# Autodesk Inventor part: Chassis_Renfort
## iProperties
Created: 2009-02
Part Number: Chassis_Renfort
Document SubType Name: Sheet Metal
Designer: claivier
Author: claivier
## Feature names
1. Perçage1 [Hole]
2. Perçage2 [Hole]
3. Plaque1
4. Pli1
5. Couper1
